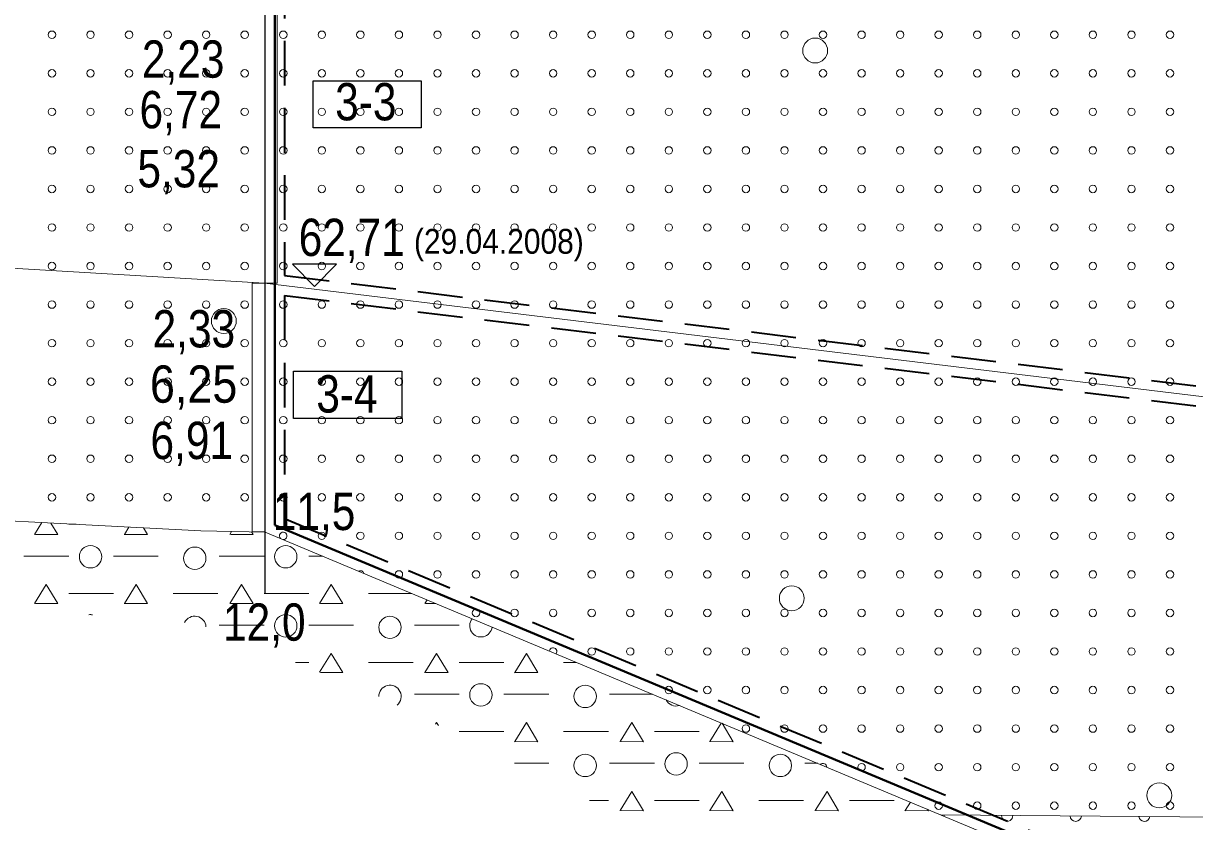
# Model space of a CAD drawing. Extents: x 640104 to 640970, y 6442278 to 6442689.
# Drawn here: x 640151 to 640245.1, y 6442521.7 to 6442585.9 of the extents above; entities that cross this region are included whole.
import ezdxf
from ezdxf.enums import TextEntityAlignment as Align

# ---------------------------------------------------------------- set-up
doc = ezdxf.new("R2010")
doc.units = 0
doc.header["$LTSCALE"] = 1.2
doc.linetypes.add('MEDIUM_DASHED', pattern=[4.5, 3, -1.5])
for name, color, linetype, lineweight in [('31', 7, 'Continuous', 13), ('32', 7, 'Continuous', 25), ('33', 7, 'Continuous', 13), ('34', 7, 'Continuous', 25), ('35', 7, 'Continuous', 35), ('42', 7, 'Continuous', 13), ('43', 7, 'Continuous', 13), ('46', 7, 'Continuous', 13), ('47', 7, 'Continuous', 13)]:
    doc.layers.add(name, color=color, linetype=linetype, lineweight=lineweight)

msp = doc.modelspace()

# ---------------------------------------------------------------- linework, layer by layer
at = {"layer": '31'}
for points in [[(640224.72, 6442522.23), (640247.13, 6442522.05), (640267.13, 6442522.88), (640278.78, 6442523.38), (640298.96, 6442524.54), (640307.35, 6442525), (640322.43, 6442526.17), (640329.85, 6442527.49), (640338.89, 6442529.33), (640344.87, 6442530.55), (640353.66, 6442533.23), (640361.47, 6442536.65), (640368.18, 6442539.82), (640375.75, 6442544.7), (640385.64, 6442551.91), (640392.23, 6442556.06), (640395.16, 6442557.52), (640398.21, 6442558.74), (640401.26, 6442559.84), (640404.41, 6442560.91), (640412.75, 6442561.86), (640417.91, 6442562.22), (640418.42, 6442562.2)], [(640136.43, 6442546.57), (640165.21, 6442545.08), (640170.39, 6442544.98), (640270.85, 6442502.92), (640281.03, 6442503.04), (640287.95, 6442503.15), (640297.33, 6442503.37), (640306.38, 6442503.93), (640319.46, 6442504.83), (640339.78, 6442506.39), (640353.27, 6442507.39), (640379.6, 6442511.07), (640396.05, 6442513.09), (640404.66, 6442514), (640412.22, 6442514.76), (640418.42, 6442515.39)]]:
    msp.add_lwpolyline(points, dxfattribs=at)
at = {"layer": '32'}
msp.add_line((640170.36, 6442660), (640170.36, 6442540), dxfattribs=at)
at = {"layer": '33'}
for points in [[(640171.36, 6442565), (640171.36, 6442600), (640170.36, 6442600), (640170.36, 6442565)], [(640169.36, 6442565), (640169.36, 6442545), (640170.36, 6442545), (640170.36, 6442565)]]:
    msp.add_lwpolyline(points, close=True, dxfattribs=at)
at = {"layer": '33', "lineweight": 25}
for points in [[(640174.24, 6442581.28), (640182.95, 6442581.28), (640182.95, 6442577.48), (640174.24, 6442577.48)], [(640172.66, 6442557.92), (640181.37, 6442557.92), (640181.37, 6442554.12), (640172.66, 6442554.12)]]:
    msp.add_lwpolyline(points, close=True, dxfattribs=at)
at = {"layer": '34', "lineweight": 13}
msp.add_lwpolyline([(640136.43, 6442567), (640170.34, 6442565), (640269.82, 6442552.96), (640308.67, 6442553.6), (640395.86, 6442553.07), (640412.35, 6442552.95), (640418.42, 6442552.96)], dxfattribs=at)
at = {"layer": '34'}
msp.add_lwpolyline([(640172.58, 6442566.53), (640174.37, 6442564.72), (640176.14, 6442566.53)], close=True, dxfattribs=at)
at = {"layer": '35', "lineweight": 40}
msp.add_line((640171.16, 6442655.36), (640171.16, 6442545.53), dxfattribs=at)
at = {"layer": '35', "linetype": 'MEDIUM_DASHED'}
for p, q in [((640171.96, 6442654.69), (640171.96, 6442565.61)), ((640171.96, 6442564), (640171.96, 6442546.06))]:
    msp.add_line(p, q, dxfattribs=at)
for points in [[(640171.96, 6442565.61), (640269.86, 6442553.76), (640308.67, 6442554.4), (640395.87, 6442553.87), (640403.06, 6442553.81)], [(640171.96, 6442564), (640269.77, 6442552.16), (640308.67, 6442552.8), (640395.86, 6442552.27), (640403.06, 6442552.21)], [(640171.96, 6442546.06), (640271.16, 6442504.53), (640281.01, 6442504.64), (640287.92, 6442504.75), (640297.26, 6442504.97), (640306.27, 6442505.53), (640319.35, 6442506.42), (640339.66, 6442507.99), (640353.1, 6442508.98), (640379.39, 6442512.65), (640395.87, 6442514.68), (640403.06, 6442515.44)]]:
    msp.add_lwpolyline(points, dxfattribs=at)
at = {"layer": '35', "lineweight": 40}
msp.add_lwpolyline([(640171.16, 6442545.53), (640271, 6442503.73), (640281.02, 6442503.84), (640287.94, 6442503.95), (640297.3, 6442504.17), (640306.32, 6442504.73), (640319.41, 6442505.62), (640339.72, 6442507.19), (640353.18, 6442508.19), (640379.49, 6442511.86), (640395.96, 6442513.88), (640403.86, 6442514.72)], dxfattribs=at)
at = {"layer": '42'}
for centre, start, end in [((640224.539, 6442522.162), 355.07231, 9.02252), ((640230.055, 6442522.162), 175.86521, 3.18966), ((640235.57, 6442522.162), 181.66015, 357.39471), ((640241.085, 6442522.162), 187.47709, 351.57777)]:
    msp.add_arc(centre, 0.45, start, end, dxfattribs=at)
at = {"layer": '43'}
for centre in [(640153.249, 6442584.973), (640156.349, 6442584.973), (640159.449, 6442584.973), (640162.549, 6442584.973), (640165.649, 6442584.973), (640168.749, 6442584.973), (640171.849, 6442584.973), (640174.949, 6442584.973), (640178.049, 6442584.973), (640181.149, 6442584.973), (640184.249, 6442584.973), (640187.349, 6442584.973), (640190.449, 6442584.973), (640193.549, 6442584.973), (640196.649, 6442584.973), (640199.749, 6442584.973), (640202.849, 6442584.973), (640205.949, 6442584.973), (640209.049, 6442584.973), (640212.149, 6442584.973), (640215.249, 6442584.973), (640218.349, 6442584.973), (640221.449, 6442584.973), (640224.549, 6442584.973), (640227.649, 6442584.973), (640230.749, 6442584.973), (640233.849, 6442584.973), (640236.949, 6442584.973), (640240.049, 6442584.973), (640243.149, 6442584.973), (640153.249, 6442581.873), (640156.349, 6442581.873), (640159.449, 6442581.873), (640162.549, 6442581.873), (640165.649, 6442581.873), (640168.749, 6442581.873), (640171.849, 6442581.873), (640174.949, 6442581.873), (640178.049, 6442581.873), (640181.149, 6442581.873), (640184.249, 6442581.873), (640187.349, 6442581.873), (640190.449, 6442581.873), (640193.549, 6442581.873), (640196.649, 6442581.873), (640199.749, 6442581.873), (640202.849, 6442581.873), (640205.949, 6442581.873), (640209.049, 6442581.873), (640212.149, 6442581.873), (640215.249, 6442581.873), (640218.349, 6442581.873), (640221.449, 6442581.873), (640224.549, 6442581.873), (640227.649, 6442581.873), (640230.749, 6442581.873), (640233.849, 6442581.873), (640236.949, 6442581.873), (640240.049, 6442581.873), (640243.149, 6442581.873), (640153.249, 6442578.773), (640156.349, 6442578.773), (640159.449, 6442578.773), (640162.549, 6442578.773), (640165.649, 6442578.773), (640168.749, 6442578.773), (640171.849, 6442578.773), (640174.949, 6442578.773), (640178.049, 6442578.773), (640181.149, 6442578.773), (640184.249, 6442578.773), (640187.349, 6442578.773), (640190.449, 6442578.773), (640193.549, 6442578.773), (640196.649, 6442578.773), (640199.749, 6442578.773), (640202.849, 6442578.773), (640205.949, 6442578.773), (640209.049, 6442578.773), (640212.149, 6442578.773), (640215.249, 6442578.773), (640218.349, 6442578.773), (640221.449, 6442578.773), (640224.549, 6442578.773), (640227.649, 6442578.773), (640230.749, 6442578.773), (640233.849, 6442578.773), (640236.949, 6442578.773), (640240.049, 6442578.773), (640243.149, 6442578.773), (640153.249, 6442575.673), (640156.349, 6442575.673), (640159.449, 6442575.673), (640162.549, 6442575.673), (640165.649, 6442575.673), (640168.749, 6442575.673), (640171.849, 6442575.673), (640174.949, 6442575.673), (640178.049, 6442575.673), (640181.149, 6442575.673), (640184.249, 6442575.673), (640187.349, 6442575.673), (640190.449, 6442575.673), (640193.549, 6442575.673), (640196.649, 6442575.673), (640199.749, 6442575.673), (640202.849, 6442575.673), (640205.949, 6442575.673), (640209.049, 6442575.673), (640212.149, 6442575.673), (640215.249, 6442575.673), (640218.349, 6442575.673), (640221.449, 6442575.673), (640224.549, 6442575.673), (640227.649, 6442575.673), (640230.749, 6442575.673), (640233.849, 6442575.673), (640236.949, 6442575.673), (640240.049, 6442575.673), (640243.149, 6442575.673), (640153.249, 6442572.573), (640156.349, 6442572.573), (640159.449, 6442572.573), (640162.549, 6442572.573), (640165.649, 6442572.573), (640168.749, 6442572.573), (640171.849, 6442572.573), (640174.949, 6442572.573), (640178.049, 6442572.573), (640181.149, 6442572.573), (640184.249, 6442572.573), (640187.349, 6442572.573), (640190.449, 6442572.573), (640193.549, 6442572.573), (640196.649, 6442572.573), (640199.749, 6442572.573), (640202.849, 6442572.573), (640205.949, 6442572.573), (640209.049, 6442572.573), (640212.149, 6442572.573), (640215.249, 6442572.573), (640218.349, 6442572.573), (640221.449, 6442572.573), (640224.549, 6442572.573), (640227.649, 6442572.573), (640230.749, 6442572.573), (640233.849, 6442572.573), (640236.949, 6442572.573), (640240.049, 6442572.573), (640243.149, 6442572.573), (640153.249, 6442569.473), (640156.349, 6442569.473), (640159.449, 6442569.473), (640162.549, 6442569.473), (640165.649, 6442569.473), (640168.749, 6442569.473), (640171.849, 6442569.473), (640174.949, 6442569.473), (640178.049, 6442569.473), (640181.149, 6442569.473), (640184.249, 6442569.473), (640187.349, 6442569.473), (640190.449, 6442569.473), (640193.549, 6442569.473), (640196.649, 6442569.473), (640199.749, 6442569.473), (640202.849, 6442569.473), (640205.949, 6442569.473), (640209.049, 6442569.473), (640212.149, 6442569.473), (640215.249, 6442569.473), (640218.349, 6442569.473), (640221.449, 6442569.473), (640224.549, 6442569.473), (640227.649, 6442569.473), (640230.749, 6442569.473), (640233.849, 6442569.473), (640236.949, 6442569.473), (640240.049, 6442569.473), (640243.149, 6442569.473), (640153.249, 6442566.373), (640156.349, 6442566.373), (640159.449, 6442566.373), (640162.549, 6442566.373), (640165.649, 6442566.373), (640168.749, 6442566.373), (640171.849, 6442566.373), (640174.949, 6442566.373), (640178.049, 6442566.373), (640181.149, 6442566.373), (640184.249, 6442566.373), (640187.349, 6442566.373), (640190.449, 6442566.373), (640193.549, 6442566.373), (640196.649, 6442566.373), (640199.749, 6442566.373), (640202.849, 6442566.373), (640205.949, 6442566.373), (640209.049, 6442566.373), (640212.149, 6442566.373), (640215.249, 6442566.373), (640218.349, 6442566.373), (640221.449, 6442566.373), (640224.549, 6442566.373), (640227.649, 6442566.373), (640230.749, 6442566.373), (640233.849, 6442566.373), (640236.949, 6442566.373), (640240.049, 6442566.373), (640243.149, 6442566.373), (640153.249, 6442563.273), (640156.349, 6442563.273), (640159.449, 6442563.273), (640162.549, 6442563.273), (640165.649, 6442563.273), (640168.749, 6442563.273), (640171.849, 6442563.273), (640174.949, 6442563.273), (640178.049, 6442563.273), (640181.149, 6442563.273), (640184.249, 6442563.273), (640187.349, 6442563.273), (640190.449, 6442563.273), (640193.549, 6442563.273), (640196.649, 6442563.273), (640199.749, 6442563.273), (640202.849, 6442563.273), (640205.949, 6442563.273), (640209.049, 6442563.273), (640212.149, 6442563.273), (640215.249, 6442563.273), (640218.349, 6442563.273), (640221.449, 6442563.273), (640224.549, 6442563.273), (640227.649, 6442563.273), (640230.749, 6442563.273), (640233.849, 6442563.273), (640236.949, 6442563.273), (640240.049, 6442563.273), (640243.149, 6442563.273), (640153.249, 6442560.173), (640156.349, 6442560.173), (640159.449, 6442560.173), (640162.549, 6442560.173), (640165.649, 6442560.173), (640168.749, 6442560.173), (640171.849, 6442560.173), (640174.949, 6442560.173), (640178.049, 6442560.173), (640181.149, 6442560.173), (640184.249, 6442560.173), (640187.349, 6442560.173), (640190.449, 6442560.173), (640193.549, 6442560.173), (640196.649, 6442560.173), (640199.749, 6442560.173), (640202.849, 6442560.173), (640205.949, 6442560.173), (640209.049, 6442560.173), (640212.149, 6442560.173), (640215.249, 6442560.173), (640218.349, 6442560.173), (640221.449, 6442560.173), (640224.549, 6442560.173), (640227.649, 6442560.173), (640230.749, 6442560.173), (640233.849, 6442560.173), (640236.949, 6442560.173), (640240.049, 6442560.173), (640243.149, 6442560.173), (640153.249, 6442557.073), (640156.349, 6442557.073), (640159.449, 6442557.073), (640162.549, 6442557.073), (640165.649, 6442557.073), (640168.749, 6442557.073), (640171.849, 6442557.073), (640174.949, 6442557.073), (640178.049, 6442557.073), (640181.149, 6442557.073), (640184.249, 6442557.073), (640187.349, 6442557.073), (640190.449, 6442557.073), (640193.549, 6442557.073), (640196.649, 6442557.073), (640199.749, 6442557.073), (640202.849, 6442557.073), (640205.949, 6442557.073), (640209.049, 6442557.073), (640212.149, 6442557.073), (640215.249, 6442557.073), (640218.349, 6442557.073), (640221.449, 6442557.073), (640224.549, 6442557.073), (640227.649, 6442557.073), (640230.749, 6442557.073), (640233.849, 6442557.073), (640236.949, 6442557.073), (640240.049, 6442557.073), (640243.149, 6442557.073), (640153.249, 6442553.973), (640156.349, 6442553.973), (640159.449, 6442553.973), (640162.549, 6442553.973), (640165.649, 6442553.973), (640168.749, 6442553.973), (640171.849, 6442553.973), (640174.949, 6442553.973), (640178.049, 6442553.973), (640181.149, 6442553.973), (640184.249, 6442553.973), (640187.349, 6442553.973), (640190.449, 6442553.973), (640193.549, 6442553.973), (640196.649, 6442553.973), (640199.749, 6442553.973), (640202.849, 6442553.973), (640205.949, 6442553.973), (640209.049, 6442553.973), (640212.149, 6442553.973), (640215.249, 6442553.973), (640218.349, 6442553.973), (640221.449, 6442553.973), (640224.549, 6442553.973), (640227.649, 6442553.973), (640230.749, 6442553.973), (640233.849, 6442553.973), (640236.949, 6442553.973), (640240.049, 6442553.973), (640243.149, 6442553.973), (640153.249, 6442550.873), (640156.349, 6442550.873), (640159.449, 6442550.873), (640162.549, 6442550.873), (640165.649, 6442550.873), (640168.749, 6442550.873), (640171.849, 6442550.873), (640174.949, 6442550.873), (640178.049, 6442550.873), (640181.149, 6442550.873), (640184.249, 6442550.873), (640187.349, 6442550.873), (640190.449, 6442550.873), (640193.549, 6442550.873), (640196.649, 6442550.873), (640199.749, 6442550.873), (640202.849, 6442550.873), (640205.949, 6442550.873), (640209.049, 6442550.873), (640212.149, 6442550.873), (640215.249, 6442550.873), (640218.349, 6442550.873), (640221.449, 6442550.873), (640224.549, 6442550.873), (640227.649, 6442550.873), (640230.749, 6442550.873), (640233.849, 6442550.873), (640236.949, 6442550.873), (640240.049, 6442550.873), (640243.149, 6442550.873), (640153.249, 6442547.773), (640156.349, 6442547.773), (640159.449, 6442547.773), (640162.549, 6442547.773), (640165.649, 6442547.773), (640168.749, 6442547.773), (640171.849, 6442547.773), (640174.949, 6442547.773), (640178.049, 6442547.773), (640181.149, 6442547.773), (640184.249, 6442547.773), (640187.349, 6442547.773), (640190.449, 6442547.773), (640193.549, 6442547.773), (640196.649, 6442547.773), (640199.749, 6442547.773), (640202.849, 6442547.773), (640205.949, 6442547.773), (640209.049, 6442547.773), (640212.149, 6442547.773), (640215.249, 6442547.773), (640218.349, 6442547.773), (640221.449, 6442547.773), (640224.549, 6442547.773), (640227.649, 6442547.773), (640230.749, 6442547.773), (640233.849, 6442547.773), (640236.949, 6442547.773), (640240.049, 6442547.773), (640243.149, 6442547.773), (640174.949, 6442544.673), (640178.049, 6442544.673), (640181.149, 6442544.673), (640184.249, 6442544.673), (640187.349, 6442544.673), (640190.449, 6442544.673), (640193.549, 6442544.673), (640196.649, 6442544.673), (640199.749, 6442544.673), (640202.849, 6442544.673), (640205.949, 6442544.673), (640209.049, 6442544.673), (640212.149, 6442544.673), (640215.249, 6442544.673), (640218.349, 6442544.673), (640221.449, 6442544.673), (640224.549, 6442544.673), (640227.649, 6442544.673), (640230.749, 6442544.673), (640233.849, 6442544.673), (640236.949, 6442544.673), (640240.049, 6442544.673), (640243.149, 6442544.673), (640181.149, 6442541.573), (640184.249, 6442541.573), (640187.349, 6442541.573), (640190.449, 6442541.573), (640193.549, 6442541.573), (640196.649, 6442541.573), (640199.749, 6442541.573), (640202.849, 6442541.573), (640205.949, 6442541.573), (640209.049, 6442541.573), (640212.149, 6442541.573), (640215.249, 6442541.573), (640218.349, 6442541.573), (640221.449, 6442541.573), (640224.549, 6442541.573), (640227.649, 6442541.573), (640230.749, 6442541.573), (640233.849, 6442541.573), (640236.949, 6442541.573), (640240.049, 6442541.573), (640243.149, 6442541.573), (640187.349, 6442538.473), (640190.449, 6442538.473), (640193.549, 6442538.473), (640196.649, 6442538.473), (640199.749, 6442538.473), (640202.849, 6442538.473), (640205.949, 6442538.473), (640209.049, 6442538.473), (640212.149, 6442538.473), (640215.249, 6442538.473), (640218.349, 6442538.473), (640221.449, 6442538.473), (640224.549, 6442538.473), (640227.649, 6442538.473), (640230.749, 6442538.473), (640233.849, 6442538.473), (640236.949, 6442538.473), (640240.049, 6442538.473), (640243.149, 6442538.473), (640196.649, 6442535.373), (640199.749, 6442535.373), (640202.849, 6442535.373), (640205.949, 6442535.373), (640209.049, 6442535.373), (640212.149, 6442535.373), (640215.249, 6442535.373), (640218.349, 6442535.373), (640221.449, 6442535.373), (640224.549, 6442535.373), (640227.649, 6442535.373), (640230.749, 6442535.373), (640233.849, 6442535.373), (640236.949, 6442535.373), (640240.049, 6442535.373), (640243.149, 6442535.373), (640202.849, 6442532.273), (640205.949, 6442532.273), (640209.049, 6442532.273), (640212.149, 6442532.273), (640215.249, 6442532.273), (640218.349, 6442532.273), (640221.449, 6442532.273), (640224.549, 6442532.273), (640227.649, 6442532.273), (640230.749, 6442532.273), (640233.849, 6442532.273), (640236.949, 6442532.273), (640240.049, 6442532.273), (640243.149, 6442532.273), (640209.049, 6442529.173), (640212.149, 6442529.173), (640215.249, 6442529.173), (640218.349, 6442529.173), (640221.449, 6442529.173), (640224.549, 6442529.173), (640227.649, 6442529.173), (640230.749, 6442529.173), (640233.849, 6442529.173), (640236.949, 6442529.173), (640240.049, 6442529.173), (640243.149, 6442529.173), (640218.349, 6442526.073), (640221.449, 6442526.073), (640224.549, 6442526.073), (640227.649, 6442526.073), (640230.749, 6442526.073), (640233.849, 6442526.073), (640236.949, 6442526.073), (640240.049, 6442526.073), (640243.149, 6442526.073), (640224.549, 6442522.973), (640227.649, 6442522.973), (640230.749, 6442522.973), (640233.849, 6442522.973), (640236.949, 6442522.973), (640240.049, 6442522.973), (640243.149, 6442522.973)]:
    msp.add_circle(centre, 0.3, dxfattribs=at)
for centre, start, end in [((640171.849, 6442544.673), 269.12364, 225.44116), ((640178.049, 6442541.573), 15.75954, 118.80526), ((640193.549, 6442535.373), 321.76208, 172.80272), ((640215.249, 6442526.073), 0.42732, 134.13748)]:
    msp.add_arc(centre, 0.3, start, end, dxfattribs=at)
at = {"layer": '46'}
for p, q in [((640155.2, 6442545.6), (640154.6, 6442545.6)), ((640154.6, 6442543.04), (640151, 6442543.04)), ((640161.8, 6442543.04), (640158.2, 6442543.04)), ((640170.3, 6442543.04), (640166.7, 6442543.04)), ((640175.03, 6442543.04), (640173.9, 6442543.04)), ((640158.2, 6442540.04), (640154.6, 6442540.04)), ((640166.6, 6442540.05), (640163, 6442540.05)), ((640173.9, 6442540.04), (640170.3, 6442540.04)), ((640182.17, 6442540.05), (640178.7, 6442540.05)), ((640184.12, 6442539.24), (640183.31, 6442539.24)), ((640170.3, 6442537.49), (640166.7, 6442537.49)), ((640177.5, 6442537.48), (640173.9, 6442537.48)), ((640185.99, 6442537.49), (640182.39, 6442537.49)), ((640173.9, 6442534.49), (640172.84, 6442534.49)), ((640182.3, 6442534.49), (640178.7, 6442534.49)), ((640189.59, 6442534.49), (640185.99, 6442534.49)), ((640195.44, 6442534.49), (640194.39, 6442534.49)), ((640185.99, 6442531.94), (640182.39, 6442531.94)), ((640193.19, 6442531.93), (640189.59, 6442531.93)), ((640201.55, 6442531.94), (640198.09, 6442531.94)), ((640189.59, 6442528.94), (640185.99, 6442528.94)), ((640197.99, 6442528.94), (640194.39, 6442528.94)), ((640205.29, 6442528.94), (640201.69, 6442528.94)), ((640193.19, 6442526.38), (640190.45, 6442526.38)), ((640201.69, 6442526.38), (640198.09, 6442526.38)), ((640208.89, 6442526.38), (640205.29, 6442526.38)), ((640214.82, 6442526.38), (640213.78, 6442526.38)), ((640197.99, 6442523.39), (640196.48, 6442523.39)), ((640205.29, 6442523.38), (640201.69, 6442523.38)), ((640213.69, 6442523.39), (640210.09, 6442523.39)), ((640220.98, 6442523.38), (640217.38, 6442523.38))]:
    msp.add_line(p, q, dxfattribs=at)
for points in [[(640151.84, 6442544.77), (640151.84, 6442544.79), (640152.43, 6442545.74)], [(640153.17, 6442545.7), (640153.72, 6442544.78), (640151.92, 6442544.79)], [(640159.06, 6442544.77), (640159.07, 6442544.79), (640159.43, 6442545.38)], [(640160.62, 6442545.32), (640160.94, 6442544.78), (640159.14, 6442544.79)], [(640167.54, 6442544.77), (640167.54, 6442544.79), (640167.69, 6442545.03)], [(640169.29, 6442545), (640169.42, 6442544.78), (640167.62, 6442544.79)], [(640151.84, 6442539.22), (640151.84, 6442539.24), (640152.79, 6442540.77), (640153.72, 6442539.23), (640151.92, 6442539.24)], [(640159.06, 6442539.22), (640159.07, 6442539.24), (640160.01, 6442540.77), (640160.94, 6442539.23), (640159.14, 6442539.24)], [(640167.54, 6442539.22), (640167.54, 6442539.24), (640168.49, 6442540.77), (640169.42, 6442539.23), (640167.62, 6442539.24)], [(640174.76, 6442539.22), (640174.76, 6442539.24), (640175.71, 6442540.77), (640176.64, 6442539.23), (640174.84, 6442539.24)], [(640183.23, 6442539.22), (640183.24, 6442539.24), (640183.41, 6442539.53)], [(640174.77, 6442533.7), (640175.71, 6442535.22), (640176.64, 6442533.68), (640174.84, 6442533.69)], [(640183.23, 6442533.66), (640183.24, 6442533.69), (640184.18, 6442535.22), (640185.11, 6442533.68), (640183.31, 6442533.69)], [(640190.45, 6442533.66), (640190.46, 6442533.69), (640191.4, 6442535.22), (640192.33, 6442533.68), (640190.53, 6442533.69)], [(640184.1, 6442529.52), (640184.18, 6442529.66), (640184.34, 6442529.41)], [(640190.45, 6442528.11), (640190.46, 6442528.13), (640191.4, 6442529.66), (640192.33, 6442528.12), (640190.53, 6442528.13)], [(640198.93, 6442528.11), (640198.93, 6442528.13), (640199.88, 6442529.66), (640200.81, 6442528.12), (640199.01, 6442528.13)], [(640206.15, 6442528.11), (640206.15, 6442528.13), (640207.07, 6442529.62)], [(640207.14, 6442529.6), (640208.03, 6442528.12), (640206.23, 6442528.13)], [(640198.93, 6442522.55), (640198.93, 6442522.58), (640199.88, 6442524.11), (640200.81, 6442522.57), (640199.01, 6442522.58)], [(640206.15, 6442522.55), (640206.15, 6442522.58), (640207.1, 6442524.11), (640208.03, 6442522.57), (640206.23, 6442522.58)], [(640214.62, 6442522.55), (640214.63, 6442522.58), (640215.57, 6442524.11), (640216.5, 6442522.57), (640214.7, 6442522.58)], [(640221.84, 6442522.55), (640221.85, 6442522.58), (640222.27, 6442523.26)], [(640223.66, 6442522.68), (640223.72, 6442522.57), (640221.92, 6442522.58)]]:
    msp.add_lwpolyline(points, dxfattribs=at)
for centre in [(640156.351, 6442542.993), (640164.733, 6442542.871), (640172.046, 6442542.993), (640172.046, 6442537.438), (640180.428, 6442537.316), (640187.741, 6442531.884), (640196.124, 6442531.762), (640196.124, 6442526.207), (640203.437, 6442526.329), (640211.819, 6442526.207)]:
    msp.add_circle(centre, 0.9, dxfattribs=at)
for centre, start, end in [((640156.351, 6442537.438), 79.58217, 98.92971), ((640164.733, 6442537.316), 2.37975, 155.00038), ((640187.741, 6442537.438), 140.6655, 353.8993), ((640180.428, 6442531.762), 308.96303, 181.33421), ((640203.437, 6442531.884), 206.40096, 288.16384)]:
    msp.add_arc(centre, 0.9, start, end, dxfattribs=at)
at = {"layer": '47'}
for centre in [(640214.617, 6442583.706), (640167.07, 6442561.947), (640212.737, 6442539.651), (640242.286, 6442523.802)]:
    msp.add_circle(centre, 1, dxfattribs=at)

# ---------------------------------------------------------------- texts
at = {"layer": '32', "width": 0.85}
for s, p in [('11,5', (640174.325, 6442545.14)), ('12,0', (640170.325, 6442536.24))]:
    msp.add_text(s, height=3, dxfattribs=at).set_placement(p, align=Align.CENTER)
at = {"layer": '33'}
for s, width, p in [('2,23', 0.85, (640163.8, 6442581.52)), ('6,72', 0.85, (640163.61, 6442577.45)), ('3-3', 0.85, (640178.485, 6442578.09)), ('5,32', 0.85, (640163.44, 6442572.7)), ('2,33', 0.85, (640164.66, 6442559.83)), ('6,25', 0.9, (640164.64, 6442555.38)), ('3-4', 0.85, (640176.97, 6442554.59)), ('6,91', 0.85, (640164.49, 6442550.85))]:
    msp.add_text(s, height=3, dxfattribs=dict(at, width=width)).set_placement(p, align=Align.CENTER)
at = {"layer": '34'}
for s, height, width, p in [('62,71', 3, 0.85, (640177.355, 6442567.18)), ('(29.04.2008)', 2, 0.9, (640189.185, 6442567.36))]:
    msp.add_text(s, height=height, dxfattribs=dict(at, width=width)).set_placement(p, align=Align.CENTER)

doc.saveas('drawing.dxf')
